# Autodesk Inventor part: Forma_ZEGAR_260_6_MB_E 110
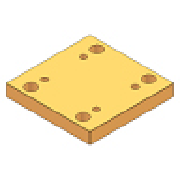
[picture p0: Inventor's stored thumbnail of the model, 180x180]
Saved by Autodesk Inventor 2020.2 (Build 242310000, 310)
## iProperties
Manager: www.cadconsulting.pl
Company: Fabian Stasiak CAD Consulting
Created: 2014-02
Part Number: Forma_ZEGAR_260_6_MB_E 110
Material: S 55 C
Description: Bottom Clamping Plate
Document SubType Name: Modeling
Designer: F.Stasiak
Standard Revision: 1
Manufacturer: DME
Language: pl-PL
Size Designation: 496x396x27
Categories: <MemberInstance><Categories><Category DisplayName="Forma wtryskowa" InternalName="349578f2-f4d4-4954-8c09-8e99297a61c0" Mnemonic="MOLD"><Category DisplayName="P
Density: 7.85 g/cm^3
Appearance: Orange (Pale)
Catalog Web Link: www.expertbooks.pl
Author: F.Stasiak
Subject: Zbiór ćwiczeń. Autodesk Inventor 2020. Kurs Professional
IsCustomPart: 1
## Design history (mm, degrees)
sketch "Sketch1"
  geometry: L1 (-198, 248)-(198, 248); L2 (198, 248)-(198, -248); L3 (198, -248)-(-198, -248); L4 (-198, -248)-(-198, 248); 5 further points
  constraints: 8 end point, 2 midpoint, 2 parallel, 1 horizontal, 1 horizontal alignment, 1 perpendicular, 1 vertical alignment
  dimensions: "d72" = 137 horizontal distance of point (0, 0) point (-137, 165) (= 0.5 x S1_W); "d73" = 165 vertical distance of point (0, 0) point (-137, 165) (= 0.5 x S1_L); "d74" = 137 horizontal distance of point (0, 0) point (-137, 208) (= 0.5 x LS_W); "d75" = 208 vertical distance of point (0, 0) point (-137, 208) (= 0.5 x LS_L); "d105" = 396 distance between parallel lines of L2 L4 (= W_); "d106" = 496 distance between parallel lines of L3 L1 (= L)
extrude "Extrusion1" new body sketch "Sketch1" distance "d20" = 27 (= H_); taper "d30" = 0 deg
hole "Hole1" sketch "Sketch1" diameter "d76" = 18 (= S1_d1); stored, may be unused: countersink angle "d80" = 90 deg, drill point angle "d82" = 0 deg; dims "d77" = 6, "d78" = 26 (= S1_d2), "d79" = 21 (= S1_k), "d81" = 27 (= H_)
pattern_linear "Rectangular Pattern1" dims "d92" = 330 (computed from S1_L, Ns), "d95" = 274 (computed from S1_W, Nw)
hole "Hole2" sketch "Sketch1" diameter "d83" = 42 (= LS_d1); stored, may be unused: countersink angle "d87" = 90 deg, drill point angle "d89" = 0 deg; dims "d84" = 6, "d85" = 26 (= S1_d2), "d86" = 21 (= S1_k), "d88" = 27 (= H_)
pattern_linear "Rectangular Pattern2" dims "d98" = 416 (computed from LS_L, Nl), "d101" = 274 (computed from LS_W, Nw)
chamfer "Chamfer1" distance "d102" = 0.5; stored, may be unused: second distance "d103" = 2, angle "d104" = 45 deg
body "Solid1"
other parameters: "L" = 496 [user parameter; used in 1 equation term], "W_" = 396 [user parameter; used in 1 equation term], "H_" = 27 [user parameter; used in 3 equation terms], "S1_W" = 274 [user parameter; used in 2 equation terms], "S1_d1" = 18 [user parameter; used in 1 equation term], "S1_d2" = 26 [user parameter; used in 2 equation terms], "S1_k" = 21 [user parameter; used in 2 equation terms], "LS_d1" = 42 [user parameter; used in 1 equation term], "LS_W" = 274 [user parameter; used in 2 equation terms], "LS_L" = 416 [user parameter; used in 2 equation terms]
